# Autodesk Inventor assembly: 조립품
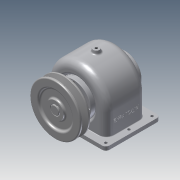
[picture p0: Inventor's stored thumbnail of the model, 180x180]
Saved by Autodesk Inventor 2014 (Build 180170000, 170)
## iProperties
Created: 2015-09
Part Number: 조립품
Document SubType Name: Assembly
Designer: sda3
Author: sda3
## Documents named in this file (14)
- C:\Users\sda3\Desktop\450907V1035\조립품.iam
- C:\Users\sda3\Desktop\450907V1035\본체.ipt
- C:\Users\sda3\Desktop\450907V1035\V-벨트풀리.ipt
- C:\Users\sda3\Desktop\450907V1035\뒤커버.ipt
- C:\Users\sda3\Desktop\450907V1035\멈춤나사 - M4x10.ipt
- C:\Users\sda3\Desktop\450907V1035\볼트 M3 x 8.ipt
- C:\Users\sda3\Desktop\450907V1035\볼트 M3 x 10.ipt
- C:\Users\sda3\Desktop\450907V1035\스퍼기어.ipt
- C:\Users\sda3\Desktop\450907V1035\앞커버.ipt
- C:\Users\sda3\Desktop\450907V1035\오일 실 17 32 8.ipt
- C:\Users\sda3\Desktop\450907V1035\축.ipt
- C:\Users\sda3\Desktop\450907V1035\키 - 5 x 5 x 18.ipt
- C:\Users\sda3\Desktop\450907V1035\키 - 6 x 6 x 22.ipt
- C:\Users\sda3\Desktop\450907V1035\베어링 6203.ipt
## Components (3 placed, 3 different names)
1. V-벨트풀리:1
2. ISO 4762 M3 x 8:1 — 각도:1
3. ISO 4762 M3 x 10:1 — 각도:2
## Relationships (2: Angle 2)
- 각도:1 [Angle]: ISO 4762 M3 x 8:1
- 각도:2 [Angle]: ISO 4762 M3 x 10:1
